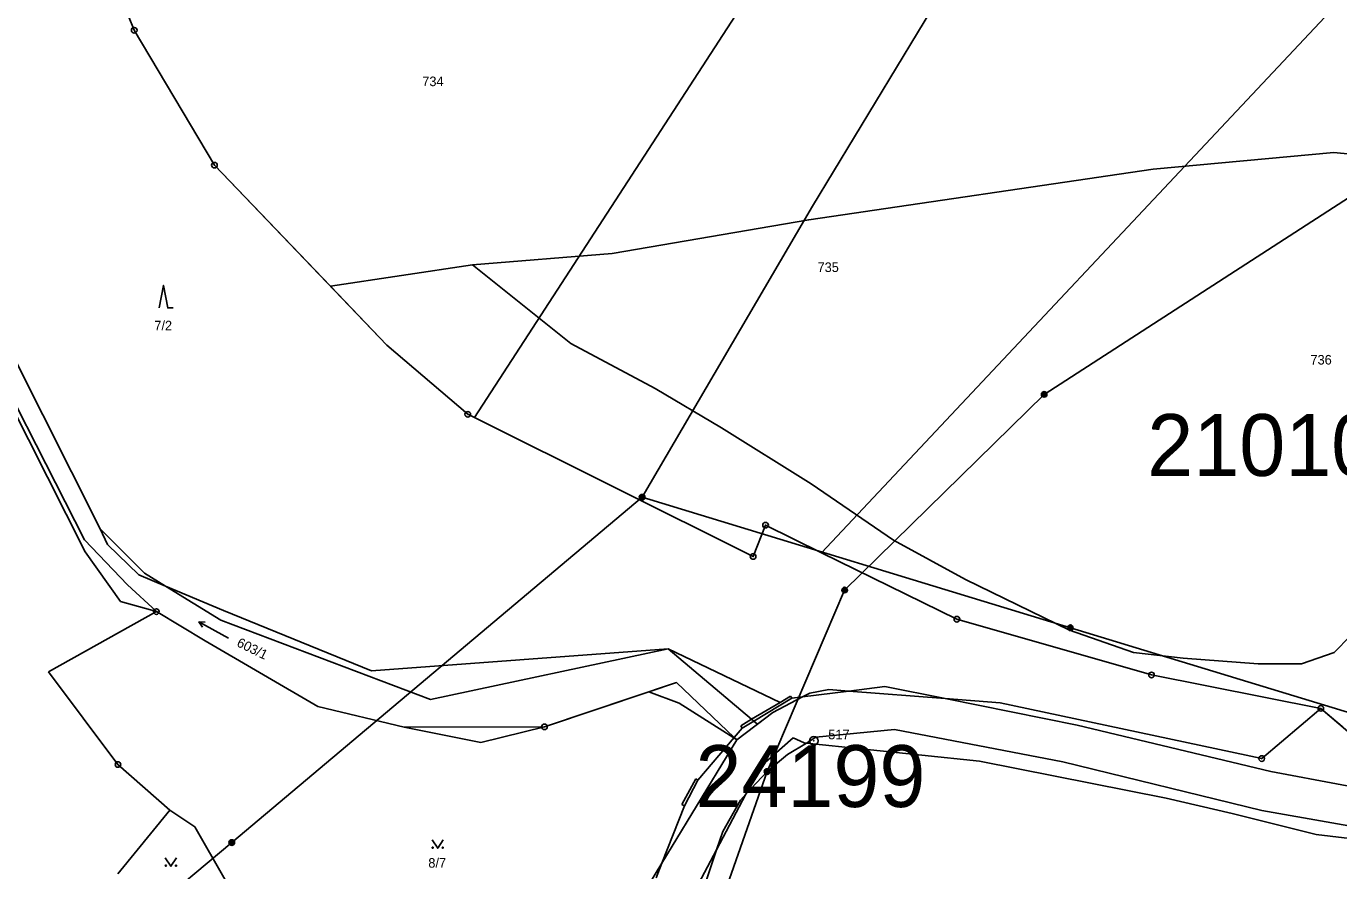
# Model space of a CAD drawing. Extents: x -725765 to -723182, y -1052705 to -1049154.
# Drawn here: x -724492.6 to -724259, y -1050931.8 to -1050781.6 of the extents above; entities that cross this region are included whole.
import ezdxf

# ---------------------------------------------------------------- set-up
doc = ezdxf.new("R2010")
doc.units = 0
for name, color, linetype in [('Vrstva 1', 7, 'Continuous'), ('Vrstva 12', 7, 'Continuous'), ('Vrstva 17', 7, 'Continuous'), ('Vrstva 18', 7, 'Continuous'), ('Vrstva 25', 7, 'Continuous'), ('Vrstva 4', 7, 'Continuous'), ('Vrstva 52', 7, 'Continuous'), ('Vrstva 53', 7, 'Continuous')]:
    doc.layers.add(name, color=color, linetype=linetype)

msp = doc.modelspace()

# ---------------------------------------------------------------- linework, layer by layer
at = {"layer": 'Vrstva 1'}
for points in [[(-724473.33, -1050782.28), (-724480.39, -1050764.74)], [(-724364.13, -1050776.24), (-724412.8, -1050851.2)], [(-724259.6, -1050778.01), (-724351.02, -1050875.23)], [(-724459.06, -1050806.28), (-724473.33, -1050782.28)], [(-724428.41, -1050838.28), (-724459.06, -1050806.28)], [(-724499.87, -1050830.41), (-724479.42, -1050870.99)], [(-724502.81, -1050832.47), (-724482.2, -1050872.94)], [(-724413.98, -1050850.61), (-724428.41, -1050838.28)], [(-724412.8, -1050851.2), (-724413.98, -1050850.61)], [(-724363.2, -1050875.91), (-724412.8, -1050851.2)], [(-724479.42, -1050870.99), (-724471.5, -1050878.85)], [(-724360.99, -1050870.33), (-724363.2, -1050875.91)], [(-724351.02, -1050875.23), (-724360.99, -1050870.33)], [(-724482.2, -1050872.94), (-724474.53, -1050880.96)], [(-724326.94, -1050887.07), (-724351.02, -1050875.23)], [(-724471.5, -1050878.85), (-724467.75, -1050881.18)], [(-724474.53, -1050880.96), (-724469.4, -1050885.71)], [(-724467.75, -1050881.18), (-724457.95, -1050887.26)], [(-724488.59, -1050896.44), (-724469.4, -1050885.71)], [(-724469.4, -1050885.71), (-724460.7, -1050890.93)], [(-724457.95, -1050887.26), (-724420.63, -1050901.33)], [(-724292.31, -1050896.98), (-724326.94, -1050887.07)], [(-724460.7, -1050890.93), (-724440.66, -1050902.59)], [(-724420.63, -1050901.33), (-724378.33, -1050892.34)], [(-724378.33, -1050892.34), (-724363.47, -1050904.87)], [(-724488.59, -1050896.44), (-724476.23, -1050912.91)], [(-724262.17, -1050902.93), (-724292.31, -1050896.98)], [(-724400.33, -1050906.21), (-724376.86, -1050898.35)], [(-724376.86, -1050898.35), (-724366.57, -1050908.12)], [(-724353.12, -1050900.21), (-724349.74, -1050899.57)], [(-724349.74, -1050899.57), (-724346.19, -1050899.85)], [(-724346.19, -1050899.85), (-724329.04, -1050901.19)], [(-724359.67, -1050903.66), (-724354.43, -1050900.9)], [(-724354.43, -1050900.9), (-724353.12, -1050900.21)], [(-724329.04, -1050901.19), (-724319.25, -1050901.96)], [(-724319.25, -1050901.96), (-724272.69, -1050911.86)], [(-724440.66, -1050902.59), (-724425.28, -1050906.29)], [(-724366.12, -1050908.55), (-724359.67, -1050903.66)], [(-724362.43, -1050905.75), (-724359.67, -1050903.66)], [(-724272.69, -1050911.86), (-724262.17, -1050902.93)], [(-724257.34, -1050907.07), (-724262.17, -1050902.93)], [(-724425.28, -1050906.29), (-724411.67, -1050908.97)], [(-724411.67, -1050908.97), (-724400.33, -1050906.21)], [(-724363.47, -1050904.87), (-724363.08, -1050905.2)], [(-724363.08, -1050905.2), (-724362.43, -1050905.75)], [(-724379.43, -1050930.49), (-724366.12, -1050908.55)], [(-724366.57, -1050908.12), (-724366.12, -1050908.55)], [(-724361.01, -1050912.5), (-724356.08, -1050908.17)], [(-724356.08, -1050908.17), (-724354.14, -1050909.06)], [(-724354.14, -1050909.06), (-724353.72, -1050909.1)], [(-724353.72, -1050909.1), (-724322.92, -1050912.35)], [(-724476.23, -1050912.91), (-724466.99, -1050921.02)], [(-724364.37, -1050918.02), (-724361.78, -1050913.76)], [(-724361.78, -1050913.76), (-724361.01, -1050912.5)], [(-724322.92, -1050912.35), (-724289.68, -1050918.92)], [(-724369.69, -1050928.08), (-724364.48, -1050918.22)], [(-724364.48, -1050918.22), (-724364.37, -1050918.02)], [(-724476.27, -1050932.34), (-724466.99, -1050921.02)], [(-724466.99, -1050921.02), (-724462.55, -1050923.98)], [(-724289.68, -1050918.92), (-724277.95, -1050921.61)], [(-724277.95, -1050921.61), (-724263.02, -1050925.34)], [(-724462.55, -1050923.98), (-724457.15, -1050933.43)], [(-724263.02, -1050925.34), (-724254.55, -1050926.36)], [(-724376.7, -1050941.33), (-724369.69, -1050928.08)], [(-724381.97, -1050934.69), (-724379.43, -1050930.49)]]:
    msp.add_lwpolyline(points, dxfattribs=at)
at = {"layer": 'Vrstva 12'}
for points in [[(-724322.72, -1050764.18), (-724352.63, -1050813.6)], [(-724311.41, -1050847.06), (-724252.23, -1050808.82)], [(-724352.63, -1050813.6), (-724382.96, -1050865.36)], [(-724346.91, -1050881.87), (-724311.41, -1050847.06)], [(-724455.97, -1050926.8), (-724382.96, -1050865.36)], [(-724382.96, -1050865.36), (-724306.75, -1050888.59)], [(-724360.72, -1050914.17), (-724346.91, -1050881.87)], [(-724229.96, -1050911.96), (-724306.75, -1050888.59)], [(-724379.33, -1050967.22), (-724360.72, -1050914.17)], [(-724501.06, -1050964.51), (-724455.97, -1050926.8)]]:
    msp.add_lwpolyline(points, dxfattribs=at)
at = {"layer": 'Vrstva 25'}
for points in [[(-724468.88, -1050831.68), (-724468.13, -1050827.68), (-724467.38, -1050831.68), (-724466.38, -1050831.68)], [(-724461.2, -1050888.48), (-724461.83, -1050887.56), (-724460.72, -1050887.6)], [(-724456.57, -1050890.44), (-724461.83, -1050887.56)], [(-724420.33, -1050926.31), (-724419.33, -1050927.81), (-724418.33, -1050926.31)], [(-724467.8, -1050929.52), (-724466.8, -1050931.02), (-724465.8, -1050929.52)]]:
    msp.add_lwpolyline(points, dxfattribs=at)
for centre, radius in [((-724473.33, -1050782.28), 0.5), ((-724473.33, -1050782.28), 0.032), ((-724459.06, -1050806.28), 0.5), ((-724459.06, -1050806.28), 0.032), ((-724311.41, -1050847.06), 0.5), ((-724311.41, -1050847.06), 0.3), ((-724311.41, -1050847.06), 0.15), ((-724413.98, -1050850.61), 0.5), ((-724413.98, -1050850.61), 0.032), ((-724382.96, -1050865.36), 0.5), ((-724382.96, -1050865.36), 0.3), ((-724382.96, -1050865.36), 0.15), ((-724360.99, -1050870.33), 0.5), ((-724360.99, -1050870.33), 0.032), ((-724363.2, -1050875.91), 0.5), ((-724363.2, -1050875.91), 0.032), ((-724346.91, -1050881.87), 0.5), ((-724346.91, -1050881.87), 0.3), ((-724346.91, -1050881.87), 0.15), ((-724469.4, -1050885.71), 0.5), ((-724469.4, -1050885.71), 0.032), ((-724326.94, -1050887.07), 0.5), ((-724326.94, -1050887.07), 0.032), ((-724306.75, -1050888.59), 0.5), ((-724306.75, -1050888.59), 0.3), ((-724306.75, -1050888.59), 0.15), ((-724292.31, -1050896.98), 0.5), ((-724292.31, -1050896.98), 0.032), ((-724262.17, -1050902.93), 0.5), ((-724262.17, -1050902.93), 0.032), ((-724400.33, -1050906.21), 0.5), ((-724400.33, -1050906.21), 0.032), ((-724352.4, -1050908.7), 0.75), ((-724352.4, -1050908.7), 0.032), ((-724272.69, -1050911.86), 0.5), ((-724476.23, -1050912.91), 0.5), ((-724476.23, -1050912.91), 0.032), ((-724360.72, -1050914.17), 0.5), ((-724360.72, -1050914.17), 0.3), ((-724360.72, -1050914.17), 0.15), ((-724272.69, -1050911.86), 0.032), ((-724455.97, -1050926.8), 0.5), ((-724455.97, -1050926.8), 0.3), ((-724455.97, -1050926.8), 0.15), ((-724420.23, -1050927.71), 0.1), ((-724418.43, -1050927.71), 0.1), ((-724467.7, -1050930.92), 0.1), ((-724465.9, -1050930.92), 0.1)]:
    msp.add_circle(centre, radius, dxfattribs=at)
at = {"layer": 'Vrstva 4'}
for points in [[(-724505.7, -1050828.43), (-724482.04, -1050875.06)], [(-724479.42, -1050870.99), (-724478.09, -1050873.79)], [(-724478.09, -1050873.79), (-724472.5, -1050879.19)], [(-724482.04, -1050875.06), (-724475.76, -1050883.92)], [(-724472.5, -1050879.19), (-724467.75, -1050881.18)], [(-724467.75, -1050881.18), (-724457.44, -1050885.49)], [(-724475.76, -1050883.92), (-724469.4, -1050885.71)], [(-724457.44, -1050885.49), (-724431.11, -1050896.22)], [(-724431.11, -1050896.22), (-724378.33, -1050892.34)], [(-724378.33, -1050892.34), (-724358.39, -1050901.87)], [(-724354.43, -1050900.9), (-724346.19, -1050899.85)], [(-724346.19, -1050899.85), (-724339.78, -1050899.03)], [(-724339.78, -1050899.03), (-724329.04, -1050901.19)], [(-724363.47, -1050904.87), (-724358.39, -1050901.87)], [(-724363.08, -1050905.2), (-724356.31, -1050901.14)], [(-724358.39, -1050901.87), (-724356.53, -1050900.77)], [(-724356.53, -1050900.77), (-724356.31, -1050901.14)], [(-724356.31, -1050901.14), (-724354.43, -1050900.9)], [(-724329.04, -1050901.19), (-724305.53, -1050905.93)], [(-724425.28, -1050906.29), (-724400.33, -1050906.21)], [(-724366.57, -1050908.12), (-724365.14, -1050906.43)], [(-724365.41, -1050906.01), (-724363.47, -1050904.87)], [(-724365.41, -1050906.01), (-724365.14, -1050906.43)], [(-724365.14, -1050906.43), (-724363.08, -1050905.2)], [(-724352.02, -1050908.07), (-724338.05, -1050906.71)], [(-724308.08, -1050912.45), (-724338.05, -1050906.71)], [(-724305.53, -1050905.93), (-724271.06, -1050914.13)], [(-724373.01, -1050915.69), (-724366.57, -1050908.12)], [(-724357.06, -1050911.14), (-724353.72, -1050909.1)], [(-724353.72, -1050909.1), (-724352.02, -1050908.07)], [(-724360.72, -1050914.17), (-724357.06, -1050911.14)], [(-724272.68, -1050921.07), (-724308.08, -1050912.45)], [(-724375.86, -1050920.04), (-724373.42, -1050915.46)], [(-724375.42, -1050920.24), (-724373.01, -1050915.69)], [(-724373.42, -1050915.46), (-724373.01, -1050915.69)], [(-724364.48, -1050918.22), (-724360.72, -1050914.17)], [(-724271.06, -1050914.13), (-724245.8, -1050918.92)], [(-724365.42, -1050919.24), (-724364.48, -1050918.22)], [(-724375.42, -1050920.24), (-724379.43, -1050930.49)], [(-724375.86, -1050920.04), (-724375.42, -1050920.24)], [(-724365.42, -1050919.24), (-724368.6, -1050924.84)], [(-724246.77, -1050925.65), (-724272.68, -1050921.07)], [(-724369.69, -1050928.08), (-724368.6, -1050924.84)], [(-724373.24, -1050938.62), (-724369.69, -1050928.08)], [(-724379.43, -1050930.49), (-724380.44, -1050933.09)]]:
    msp.add_lwpolyline(points, dxfattribs=at)
at = {"layer": 'Vrstva 52'}
for points in [[(-724581.64, -1050708.13), (-724564.23, -1050728.57), (-724563.61, -1050729.23), (-724540.92, -1050753.35), (-724516.71, -1050779.1), (-724513.92, -1050781.58), (-724511.8, -1050807.6), (-724502.81, -1050832.47), (-724482.2, -1050872.94), (-724474.53, -1050880.96), (-724469.4, -1050885.71), (-724460.7, -1050890.93), (-724440.66, -1050902.59), (-724425.28, -1050906.29), (-724411.67, -1050908.97), (-724400.33, -1050906.21), (-724381.77, -1050899.99)], [(-724487.5, -1050734.82), (-724480.39, -1050764.74), (-724473.33, -1050782.28), (-724459.06, -1050806.28), (-724438.42, -1050827.83)], [(-724413.13, -1050824), (-724388.31, -1050822), (-724353.31, -1050816), (-724292, -1050807), (-724259.88, -1050804), (-724250.19, -1050805), (-724239, -1050808), (-724225.63, -1050816), (-724213.63, -1050828), (-724198.13, -1050849)], [(-724438.42, -1050827.83), (-724413.13, -1050824)], [(-724413.13, -1050824), (-724395.63, -1050838), (-724380.63, -1050846), (-724368.81, -1050853), (-724352.88, -1050863), (-724338.19, -1050873), (-724325.38, -1050880), (-724306.88, -1050889), (-724295.5, -1050893), (-724286.69, -1050894), (-724273.31, -1050895), (-724265.63, -1050895), (-724259.81, -1050893), (-724256.88, -1050890), (-724249.69, -1050879), (-724239.88, -1050868), (-724231.13, -1050860), (-724221.31, -1050854), (-724209.63, -1050849), (-724200.13, -1050848), (-724198.13, -1050849)], [(-724438.42, -1050827.83), (-724428.41, -1050838.28), (-724413.98, -1050850.61), (-724412.8, -1050851.2), (-724363.2, -1050875.91), (-724360.99, -1050870.33), (-724351.02, -1050875.23), (-724326.94, -1050887.07), (-724292.31, -1050896.98), (-724262.17, -1050902.93), (-724258.37, -1050906.18)], [(-724381.77, -1050899.99), (-724376.86, -1050898.35), (-724366.57, -1050908.12), (-724366.18, -1050908.49)], [(-724381.77, -1050899.99), (-724376.38, -1050902), (-724366.18, -1050908.49)], [(-724366.18, -1050908.49), (-724366.12, -1050908.55), (-724379.43, -1050930.49), (-724381.97, -1050934.69)]]:
    msp.add_lwpolyline(points, dxfattribs=at)

# ---------------------------------------------------------------- texts
at = {"layer": 'Vrstva 17'}
msp.add_text('517 ', height=1.7, dxfattribs=at).set_placement((-724349.83, -1050908.43))
at = {"layer": 'Vrstva 18'}
for s, p in [('734', (-724422.08, -1050792.22)), ('735', (-724351.74, -1050825.29)), ('7/2', (-724469.76, -1050835.67)), ('736', (-724264.02, -1050841.75)), ('8/7', (-724421, -1050931.27))]:
    msp.add_text(s, height=1.7, dxfattribs=at).set_placement(p)
msp.add_text('603/1', height=1.7, rotation=333.9027, dxfattribs=at).set_placement((-724455.23, -1050891.8))
at = {"layer": 'Vrstva 53'}
for s, p in [('21010', (-724293.05, -1050861.57)), ('24199', (-724373.45, -1050920.48))]:
    msp.add_text(s, height=11, dxfattribs=at).set_placement(p)

doc.saveas('drawing.dxf')
